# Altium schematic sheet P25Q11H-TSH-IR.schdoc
size 127 x 101 mm
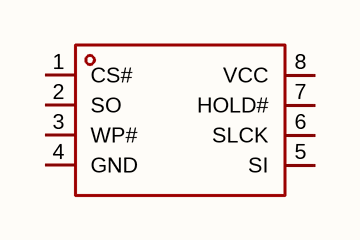
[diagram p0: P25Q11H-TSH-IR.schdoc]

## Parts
U?  p25q11h-tsh-ir  [TSSOP-8_L4.4-W3.0-P0.65-LS6.4-BL]  (value not drawn)

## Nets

Not connected (* = marked no-connect by the designer): U? 1(CS#) 2(SO) 3(WP#) 4(GND) 5(SI) 6(SLCK) 7(HOLD#) 8(VCC)

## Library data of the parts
U? = p25q11h-tsh-ir: 接口类型:SPI;存储容量:1Mbit;时钟频率(fc):104MHz;; Manufacturer: PUYA(普冉); AddInBom: yes; ModelId: 85577802f9634e7e85ffa2fd25a37b6f; ModelName: TSSOP-8_L4.4-W3.0-P0.65-LS6.4-BL-2; ModelTransform: 118.11,251.968,0,0,0,0,0,0,0; Interface: SPI; Memory Size: 1Mbit; Clock Frequency: 104MHz; Voltage - Supply: 2.3V~3.6V; Standby Supply Current: 9uA; Program / Erase Cycles: 100000次; Page Programming Time (Tpp): 2ms; Block Erase Time(tBE): 8ms@(64KB); Data Retention - TDR (Year): 20年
